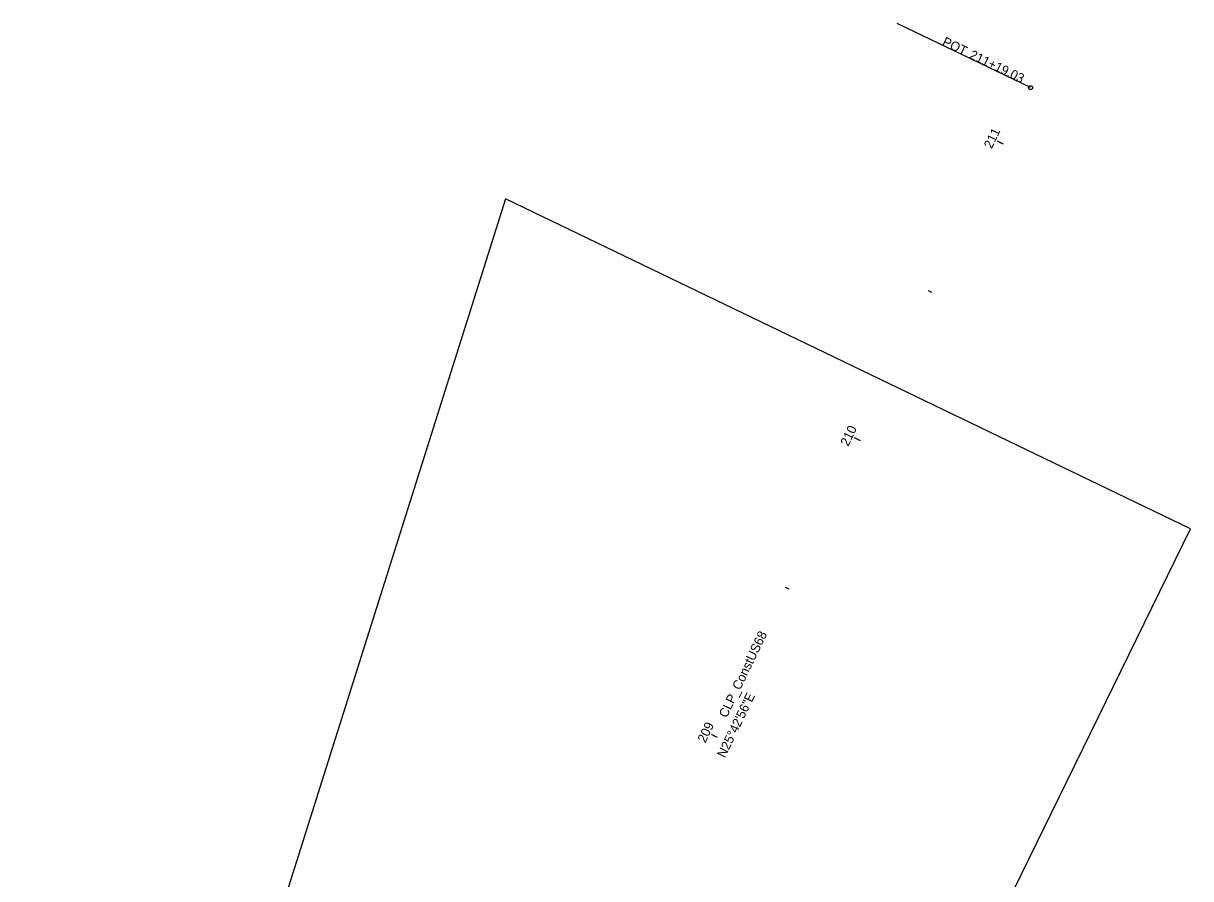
# Model space of a CAD drawing. Extents: x 1564517 to 1565226, y 635740 to 637455.
# Drawn here: x 1564871.5 to 1565225.9, y 637041.9 to 637301.6 of the extents above; entities that cross this region are included whole.
import ezdxf

# ---------------------------------------------------------------- set-up
doc = ezdxf.new("R2010")
doc.units = 0
for name, color, linetype in [('GE_P_Alignment_1000_Bearings', 7, 'Continuous'), ('GE_P_Alignment_1000_Distances', 7, 'Continuous'), ('GE_P_Alignment_100_Cardinal_Points', 7, 'Continuous'), ('GE_P_Alignment_500_Bearings', 7, 'Continuous'), ('GE_P_Alignment_500_Cardinal_Points', 7, 'Continuous'), ('GE_P_Alignment_500_Distances', 7, 'Continuous'), ('UT_P_Water_Cells', 7, 'Continuous'), ('UT_X_Electric', 7, 'Continuous'), ('UT_X_Sanitary_Pressure_Line', 7, 'Continuous'), ('UT_X_Water_Cells', 7, 'Continuous')]:
    doc.layers.add(name, color=color, linetype=linetype)

msp = doc.modelspace()

# ---------------------------------------------------------------- linework, layer by layer
at = {"layer": 'GE_P_Alignment_100_Cardinal_Points'}
msp.add_circle((1565177.32, 637282.11), 0.6, dxfattribs=at)
at = {"layer": 'GE_P_Alignment_500_Cardinal_Points'}
msp.add_line((1565177.32, 637282.11), (1565136.78, 637301.64), dxfattribs=at)
msp.add_circle((1565177.32, 637282.11), 0.6, dxfattribs=at)
at = {"layer": 'UT_P_Water_Cells'}
for p, q in [((1565169.06, 637264.97), (1565167.98, 637265.49)), ((1565125.67, 637174.87), (1565123.87, 637175.74)), ((1565082.28, 637084.78), (1565081.2, 637085.3))]:
    msp.add_line(p, q, dxfattribs=at)
at = {"layer": 'UT_X_Electric'}
msp.add_lwpolyline([(1564858.24, 636742.53), (1565001.39, 636689.39), (1565225.94, 637148.15), (1565017.94, 637248.32)], close=True, dxfattribs=at)
at = {"layer": 'UT_X_Sanitary_Pressure_Line'}
msp.add_line((1565125.67, 637174.87), (1565123.87, 637175.74), dxfattribs=at)
at = {"layer": 'UT_X_Water_Cells'}
for p, q in [((1565169.06, 637264.97), (1565167.26, 637265.83)), ((1565147.37, 637219.92), (1565146.29, 637220.44)), ((1565125.67, 637174.87), (1565123.87, 637175.74)), ((1565103.98, 637129.82), (1565102.9, 637130.34)), ((1565082.28, 637084.78), (1565080.48, 637085.64))]:
    msp.add_line(p, q, dxfattribs=at)

# ---------------------------------------------------------------- texts
at = {"layer": 'GE_P_Alignment_1000_Bearings'}
msp.add_text('N25°42\'56"E', height=2.8, rotation=64.2844, dxfattribs=at).set_placement((1565084.53, 637078.37))
at = {"layer": 'GE_P_Alignment_1000_Distances'}
msp.add_text('CLP_ConstUS68', height=2.8, rotation=64.2844, dxfattribs=at).set_placement((1565085.05, 637090.53))
at = {"layer": 'GE_P_Alignment_500_Bearings'}
msp.add_text('N25°42\'56"E', height=2.8, rotation=64.2844, dxfattribs=at).set_placement((1565084.53, 637078.37))
at = {"layer": 'GE_P_Alignment_500_Cardinal_Points'}
for s, p in [('POT', (1565150.29, 637295.13)), ('211+19.03', (1565158.52, 637291.17))]:
    msp.add_text(s, height=2.8, rotation=334.2844, dxfattribs=at).set_placement(p)
at = {"layer": 'GE_P_Alignment_500_Distances'}
msp.add_text('CLP_ConstUS68', height=2.8, rotation=64.2844, dxfattribs=at).set_placement((1565085.05, 637090.53))
at = {"layer": 'UT_P_Water_Cells'}
msp.add_text('210', height=2.8, rotation=64.2844, dxfattribs=at).set_placement((1565121.95, 637173.02))
at = {"layer": 'UT_X_Sanitary_Pressure_Line'}
msp.add_text('210', height=2.8, rotation=64.2844, dxfattribs=at).set_placement((1565121.95, 637173.02))
at = {"layer": 'UT_X_Water_Cells'}
for s, p in [('211', (1565165.52, 637263.38)), ('210', (1565121.95, 637173.02)), ('209', (1565078.58, 637082.95))]:
    msp.add_text(s, height=2.8, rotation=64.2844, dxfattribs=at).set_placement(p)

doc.saveas('drawing.dxf')
